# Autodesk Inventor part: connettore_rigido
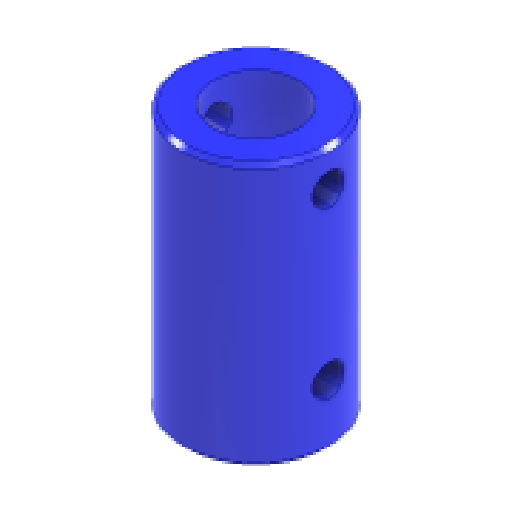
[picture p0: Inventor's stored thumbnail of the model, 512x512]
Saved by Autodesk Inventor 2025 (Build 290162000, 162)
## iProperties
Created: 2025-04
Part Number: connettore_rigido
Material: Alluminio 6061
Document SubType Name: Modeling
Designer: R5800u
Density: 2.7 g/cm^3
Appearance: Blu - Pittura muro - Lucida
Author: R5800u
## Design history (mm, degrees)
sketch "Schizzo1"
  geometry: C1 r 7 at (0, 0); C2 r 2.5 at (0, 0); 1 further point
  constraints: 2 centre point, 2 coincident
  dimensions: "d0" = 14 diameter of C1; "d1" = 5 diameter of C2
extrude "Estrusione1" new body sketch "Schizzo1" distance "d2" = 25; taper "d3" = 0 deg
sketch "Schizzo2"
  geometry: C1 r 4 at (0, 0); 1 further point
  constraints: 1 centre point, 1 coincident
  dimensions: "d4" = 8 diameter of C1
extrude "Estrusione2" cut sketch "Schizzo2" distance "d5" = 14.5; taper "d6" = 0 deg
sketch "Schizzo3"
  geometry: C1 r 1.5 at (19.936, 0); C2 r 1.5 at (5.75, 0); 3 further points
  constraints: 2 centre point, 2 coincident
  dimensions: "d7" = 3 diameter of C1; "d8" = 3 diameter of C2
extrude "Estrusione3" cut sketch "Schizzo3" extent not by distance; stored distance "d9" = 12.5; taper "d10" = 0 deg
chamfer "Smusso1" distance "d11" = 0.4; stored, may be unused: second distance "d12" = 2, angle "d13" = 45 deg
node "Solido1"
